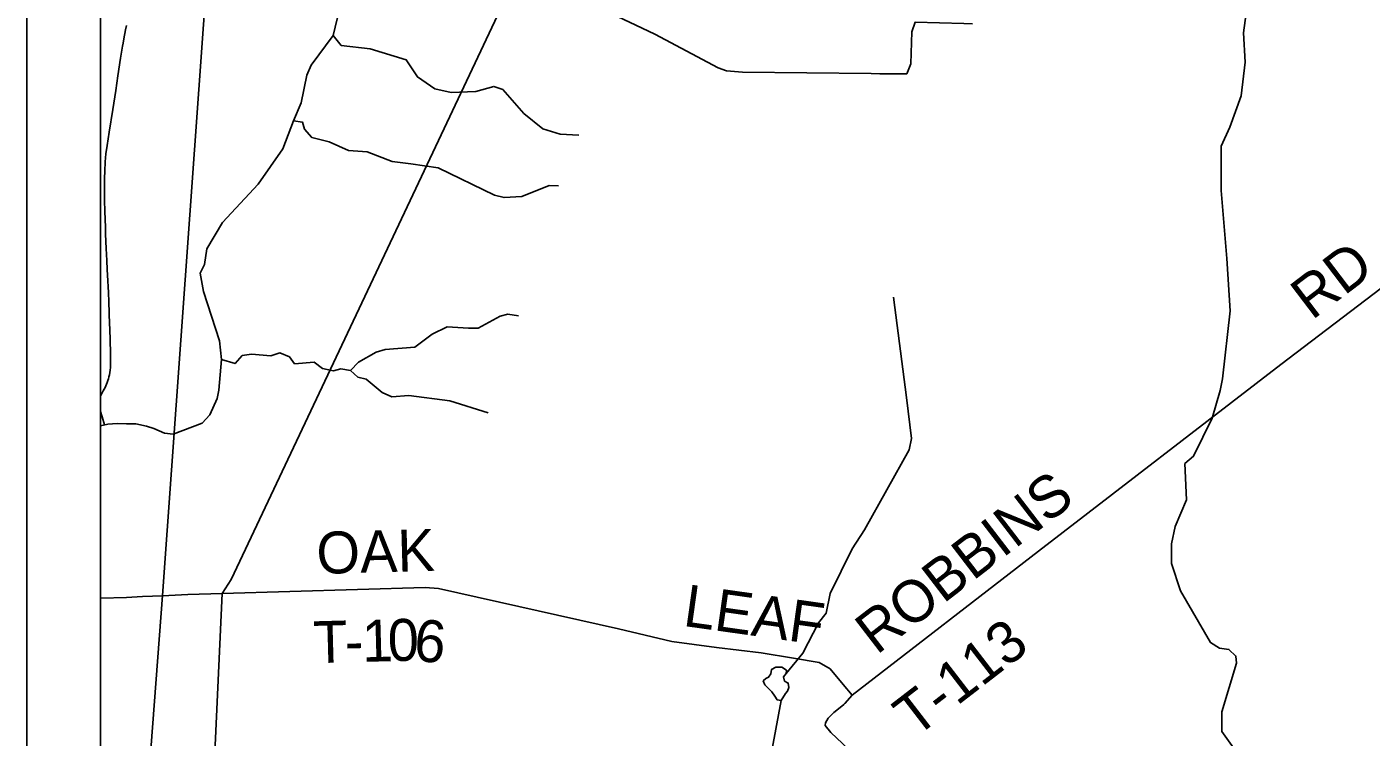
# Model space of a CAD drawing. Extents: x 0 to 34, y 0 to 22.
# Drawn here: x 2 to 3.822, y 15.554 to 16.516 of the extents above; entities that cross this region are included whole.
import ezdxf

# ---------------------------------------------------------------- set-up
doc = ezdxf.new("R2010")
doc.units = 0
for name, color, linetype in [('Default', 7, 'Continuous'), ('GM_X_County_Road', 7, 'Continuous'), ('GM_X_Minor_Lake', 7, 'Continuous'), ('GM_X_Minor_River', 7, 'Continuous'), ('GM_X_Township_Road', 7, 'Continuous'), ('GM_X_Township_Road_Text', 7, 'Continuous'), ('SH_Cut_Line', 7, 'Continuous'), ('SH_Data', 7, 'Continuous')]:
    doc.layers.add(name, color=color, linetype=linetype)

msp = doc.modelspace()

# ---------------------------------------------------------------- linework, layer by layer
at = {"layer": 'Default'}
msp.add_lwpolyline([(2.4006, 20.8941), (2.1, 20.8941), (2.1, 14.637), (2.1837, 15.746), (2.258, 16.7775), (2.2632, 16.8811), (2.2668, 17.0936), (2.2797, 17.8302), (2.3212, 18.6531), (2.3791, 20.1601)], close=True, dxfattribs=at)
msp.add_lwpolyline([(2.3212, 18.6531), (2.2797, 17.8302), (2.2668, 17.0936), (2.2632, 16.8811), (2.258, 16.7775), (2.1837, 15.746), (2.1, 14.637), (2.1, 14.4457), (2.4012, 14.4298), (2.4436, 14.4284), (2.5802, 14.4232), (3.783, 14.3901), (4.0144, 14.3862), (4.819, 14.3535), (4.9366, 14.3421), (5.2368, 14.8438), (5.4205, 15.1508), (5.9071, 15.964)], dxfattribs=at)
at = {"layer": 'GM_X_County_Road'}
for points in [[(2.5764, 14.4716), (2.576, 14.4765), (2.5609, 14.9423), (2.3292, 14.9976), (2.3149, 15.0036), (2.301, 15.0111), (2.2909, 15.02), (2.2825, 15.0399), (2.2772, 15.0643), (2.2466, 15.3567), (2.2648, 15.7486), (2.2769, 15.7675), (2.5348, 16.3135), (2.661, 16.5806), (2.7462, 16.7548), (2.8161, 16.9004), (2.88, 17.0272), (2.8992, 17.0651), (2.9226, 17.1033), (2.9413, 17.129), (2.9624, 17.1442), (3.1172, 17.2356), (3.321, 17.3562)], [(2.1, 16.0159), (2.1036, 16.023), (2.1061, 16.0276), (2.1071, 16.0299), (2.1081, 16.0319), (2.109, 16.0343), (2.1098, 16.0368), (2.1106, 16.0395), (2.1113, 16.0421), (2.112, 16.0449), (2.1125, 16.0478), (2.1129, 16.0512), (2.1132, 16.0546), (2.1134, 16.0573), (2.1135, 16.0616), (2.1135, 16.0686), (2.1134, 16.0748), (2.113, 16.0907), (2.1124, 16.1074), (2.1122, 16.1133), (2.111, 16.1437), (2.1105, 16.1564), (2.1093, 16.1798), (2.1088, 16.1875), (2.1083, 16.1994), (2.1076, 16.2159), (2.1068, 16.2353), (2.1065, 16.2439), (2.1061, 16.256), (2.1058, 16.2654), (2.1054, 16.2818), (2.1053, 16.2893), (2.1053, 16.3017), (2.1054, 16.311), (2.1056, 16.3204), (2.1061, 16.3334), (2.1072, 16.3442), (2.1087, 16.3554), (2.1116, 16.3736), (2.1165, 16.4043), (2.1205, 16.43), (2.1235, 16.4499), (2.1271, 16.4736), (2.1288, 16.4844), (2.1297, 16.4898), (2.1304, 16.4941), (2.1314, 16.4998), (2.1337, 16.5119), (2.1351, 16.5177)]]:
    msp.add_lwpolyline(points, dxfattribs=at)
at = {"layer": 'GM_X_Minor_Lake'}
for points in [[(3.0283, 15.6131), (3.031, 15.6161), (3.0329, 15.621), (3.0323, 15.6271), (3.027, 15.6298), (3.0256, 15.6356), (3.0295, 15.64), (3.0299, 15.6446), (3.0235, 15.6485), (3.0152, 15.6486), (3.0095, 15.6457), (3.0086, 15.6396), (3.0055, 15.6351), (3.0017, 15.6333), (2.9982, 15.63), (3.0004, 15.625), (3.0056, 15.62), (3.0101, 15.6153), (3.0138, 15.6096), (3.0171, 15.6046), (3.0228, 15.6034)], [(3.0228, 15.6034), (3.0283, 15.6131)]]:
    msp.add_lwpolyline(points, dxfattribs=at)
at = {"layer": 'GM_X_Minor_River'}
for points in [[(2.4287, 16.7112), (2.4527, 16.7203), (2.4655, 16.714), (2.5037, 16.7092), (2.5275, 16.6811), (2.5979, 16.6447), (2.6084, 16.6381), (2.6431, 16.6034), (2.669, 16.5859), (2.7835, 16.5384), (2.8512, 16.5062), (2.9373, 16.4604), (2.9483, 16.4564), (2.9702, 16.4545), (3.1446, 16.4529), (3.1564, 16.4524), (3.1928, 16.4525), (3.1983, 16.466), (3.1998, 16.5095), (3.2042, 16.5223), (3.2701, 16.5204), (3.2818, 16.5202)], [(3.6356, 15.5395), (3.6201, 15.5614), (3.6202, 15.5883), (3.6398, 15.6543), (3.6392, 15.6638), (3.6295, 15.6727), (3.6167, 15.6745), (3.6047, 15.6819), (3.5638, 15.752), (3.5519, 15.789), (3.5516, 15.8159), (3.5569, 15.8393), (3.5723, 15.8754), (3.5697, 15.9244), (3.5816, 15.9344), (3.6071, 15.9859), (3.6176, 16.0236), (3.6209, 16.0391), (3.6311, 16.1314), (3.6266, 16.2023), (3.619, 16.2942), (3.6189, 16.3544), (3.6307, 16.3803), (3.6461, 16.4225), (3.6518, 16.4682), (3.6494, 16.508), (3.6576, 16.5685)], [(2.4297, 16.565), (2.4151, 16.5043), (2.3856, 16.4643), (2.3797, 16.4504), (2.3719, 16.413), (2.3616, 16.3886), (2.347, 16.351), (2.3136, 16.303), (2.2653, 16.2512), (2.2439, 16.2156), (2.2408, 16.194), (2.235, 16.1824), (2.2395, 16.1577), (2.2611, 16.0909), (2.2637, 16.0655), (2.2604, 16.0239), (2.2579, 16.0125), (2.2481, 15.9903), (2.2376, 15.9791), (2.1983, 15.9642)], [(2.4151, 16.5043), (2.4263, 16.4909), (2.4656, 16.4864), (2.5143, 16.4712), (2.5295, 16.4482), (2.5531, 16.4322), (2.575, 16.4273), (2.6088, 16.4286), (2.6332, 16.4354), (2.6452, 16.431), (2.6735, 16.3987), (2.6994, 16.3778), (2.7231, 16.3709), (2.7485, 16.3694)], [(2.3616, 16.3886), (2.3737, 16.3869), (2.3762, 16.3773), (2.3863, 16.3662), (2.4097, 16.3601), (2.4361, 16.3486), (2.4611, 16.3467), (2.4954, 16.3336), (2.5207, 16.3305), (2.5578, 16.3253), (2.6338, 16.288), (2.647, 16.2847), (2.6709, 16.2862), (2.708, 16.3011), (2.7205, 16.3005)], [(3.0295, 15.64), (3.0519, 15.6677), (3.0731, 15.7087), (3.0836, 15.7218), (3.089, 15.7486), (3.1188, 15.8091), (3.1355, 15.8346), (3.1961, 15.9431), (3.1994, 15.9586), (3.1924, 16.0141), (3.1749, 16.1501)], [(2.4387, 16.0507), (2.4495, 16.0619), (2.4736, 16.0755), (2.4858, 16.0791), (2.5261, 16.0822), (2.5495, 16.1), (2.5698, 16.1095), (2.5986, 16.1078), (2.6118, 16.108), (2.6417, 16.1241), (2.652, 16.127), (2.6664, 16.1245)], [(2.2637, 16.0655), (2.2822, 16.0599), (2.2919, 16.0711), (2.3044, 16.0728), (2.3306, 16.0704), (2.3428, 16.0744), (2.356, 16.0692), (2.363, 16.0596), (2.3896, 16.0618), (2.4008, 16.0533), (2.4159, 16.05), (2.4255, 16.0528), (2.4387, 16.0507), (2.4488, 16.0414), (2.4598, 16.039), (2.4818, 16.0208), (2.4946, 16.0149), (2.5178, 16.0167), (2.5734, 16.0093), (2.6255, 15.9933)], [(2.1052, 15.9768), (2.1021, 15.9879), (2.1, 15.9951)], [(2.1983, 15.9642), (2.1866, 15.9655), (2.1719, 15.9722), (2.1621, 15.9753), (2.1478, 15.9782), (2.1349, 15.9783), (2.1224, 15.9789), (2.1099, 15.9779), (2.1, 15.9757)], [(3.0327, 15.3366), (3.0496, 15.4425), (3.046, 15.4547), (3.0157, 15.4969), (3.0095, 15.5331), (3.0119, 15.5455), (3.0228, 15.6034)]]:
    msp.add_lwpolyline(points, dxfattribs=at)
at = {"layer": 'GM_X_Township_Road'}
for points in [[(3.1188, 15.6106), (3.3713, 15.8058), (3.7002, 16.0586), (3.9927, 16.2813)], [(2.1, 15.7422), (2.1002, 15.7422), (2.1349, 15.7432), (2.1567, 15.7443), (2.1839, 15.7455)], [(2.1839, 15.7455), (2.2184, 15.7473), (2.2648, 15.7486), (2.5398, 15.7566), (2.558, 15.7551), (2.8019, 15.7006), (2.8745, 15.6837), (2.9347, 15.6754), (2.9953, 15.6682), (3.0392, 15.6609), (3.074, 15.655), (3.0891, 15.6463), (3.1065, 15.6252), (3.1188, 15.6106), (3.1089, 15.5997)], [(3.1089, 15.5997), (3.1076, 15.5982), (3.1001, 15.5922), (3.0941, 15.5874), (3.0864, 15.5796), (3.0829, 15.5732), (3.0824, 15.5695), (3.0899, 15.5602), (3.2729, 15.3876), (3.4334, 15.2332), (3.6407, 15.0353)]]:
    msp.add_lwpolyline(points, dxfattribs=at)
at = {"layer": 'SH_Cut_Line'}
msp.add_lwpolyline([(2.4006, 20.8941), (2.1, 20.8941), (2.1, 14.637), (2.1837, 15.746), (2.258, 16.7775), (2.2632, 16.8811), (2.2668, 17.0936), (2.2797, 17.8302), (2.3212, 18.6531), (2.3791, 20.1601)], close=True, dxfattribs=at)
msp.add_lwpolyline([(2.3212, 18.6531), (2.2797, 17.8302), (2.2668, 17.0936), (2.2632, 16.8811), (2.258, 16.7775), (2.1837, 15.746), (2.1, 14.637), (2.1, 14.4457), (2.4012, 14.4298), (2.4436, 14.4284), (2.5802, 14.4232), (3.783, 14.3901), (4.0144, 14.3862), (4.819, 14.3535), (4.9366, 14.3421), (5.0616, 14.3309), (5.4793, 14.3187), (6.7418, 14.3069), (6.8864, 14.3056), (7.3204, 14.3032), (8.6074, 14.2911), (8.7041, 14.2905), (8.9, 14.2922), (8.9, 20.8941)], dxfattribs=at)
at = {"layer": 'SH_Data'}
for p, q in [((2, 21), (2, 14)), ((2.1, 20.9), (2.1, 14.1))]:
    msp.add_line(p, q, dxfattribs=at)

# ---------------------------------------------------------------- texts
at = {"layer": 'GM_X_Township_Road_Text'}
for s, height, rotation, p in [('RD', 0.05682, 37.2663, (3.7421, 16.1179)), ('ROBBINS', 0.05682, 37.5682, (3.152, 15.6645)), ('OAK', 0.05682, 1.5776, (2.3933, 15.7749)), ('LEAF', 0.05682, 352.0134, (2.8883, 15.7048)), ('T', 0.0568, 1.5559, (2.3891, 15.654)), ('1', 0.0568, 1.5197, (2.4549, 15.6558)), ('0', 0.0568, 1.3948, (2.4899, 15.6567)), ('6', 0.0568, 354.8828, (2.5232, 15.6576)), ('T-113', 0.05682, 37.6031, (3.2041, 15.552)), ('-', 0.0568, 1.5458, (2.4316, 15.6552))]:
    msp.add_text(s, height=height, rotation=rotation, dxfattribs=at).set_placement(p)

doc.saveas('drawing.dxf')
